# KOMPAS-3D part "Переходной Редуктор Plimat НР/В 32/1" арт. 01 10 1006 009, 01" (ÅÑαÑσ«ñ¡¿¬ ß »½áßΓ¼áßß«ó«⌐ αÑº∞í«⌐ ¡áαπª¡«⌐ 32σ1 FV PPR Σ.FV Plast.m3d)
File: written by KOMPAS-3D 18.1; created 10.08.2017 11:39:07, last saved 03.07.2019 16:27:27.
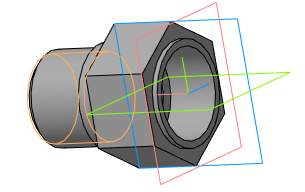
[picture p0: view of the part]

Document properties: Автор: Мирончук; Организация: Мирончук; Полное имя файла: D:\Magna\Магна Ins\Магна ins 10\М10-00.00.000\3Д\Переходник с пластмассовой резьбой наружной 32х1 FV PPR ф.FV Plast.m3d

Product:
- Part/product: Переходной Редуктор Plimat НР/В 32/1" арт. 01 10 1006 009  | designation 01
    Масса: 0.0328755
    Раздел спецификации: Прочие изделия
- Part/product: Переходник с пластмассовой резьбой  / наружной 32х1" FV PPR  / ф. "FV PLAST"
    Масса: 0.0328755
    Раздел спецификации: Прочие изделия

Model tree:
1. Эскиз:1
2. Операция вращения:1
     Угол 1 = 360
3. Условное изображение резьбы:2  (labels: G 1)
     Длина резьбы = 23; Шаг резьбы = 2.309; Номинальный диаметр резьбы = 33.249
4. Подгонка:1
5. Эскиз:9
6. Вырезать элемент выдавливания:7
     Расстояние 1 = 32
7. Эскиз:10
8. Вырезать элемент выдавливания:8
     Расстояние 1 = 7
9. Эскиз:11
10. Вырезать элемент выдавливания:9
     Расстояние 1 = 2
11. Фаска:3  (labels: D4)
     Угол = 45; Длина 1 = 2.5; Длина 2 = 2.5

Expressions: D/2; d/2; G/2; D4/2; cil2_6357-81
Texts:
  Body Specification ( left align )
  Body Specificaton ( centered )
